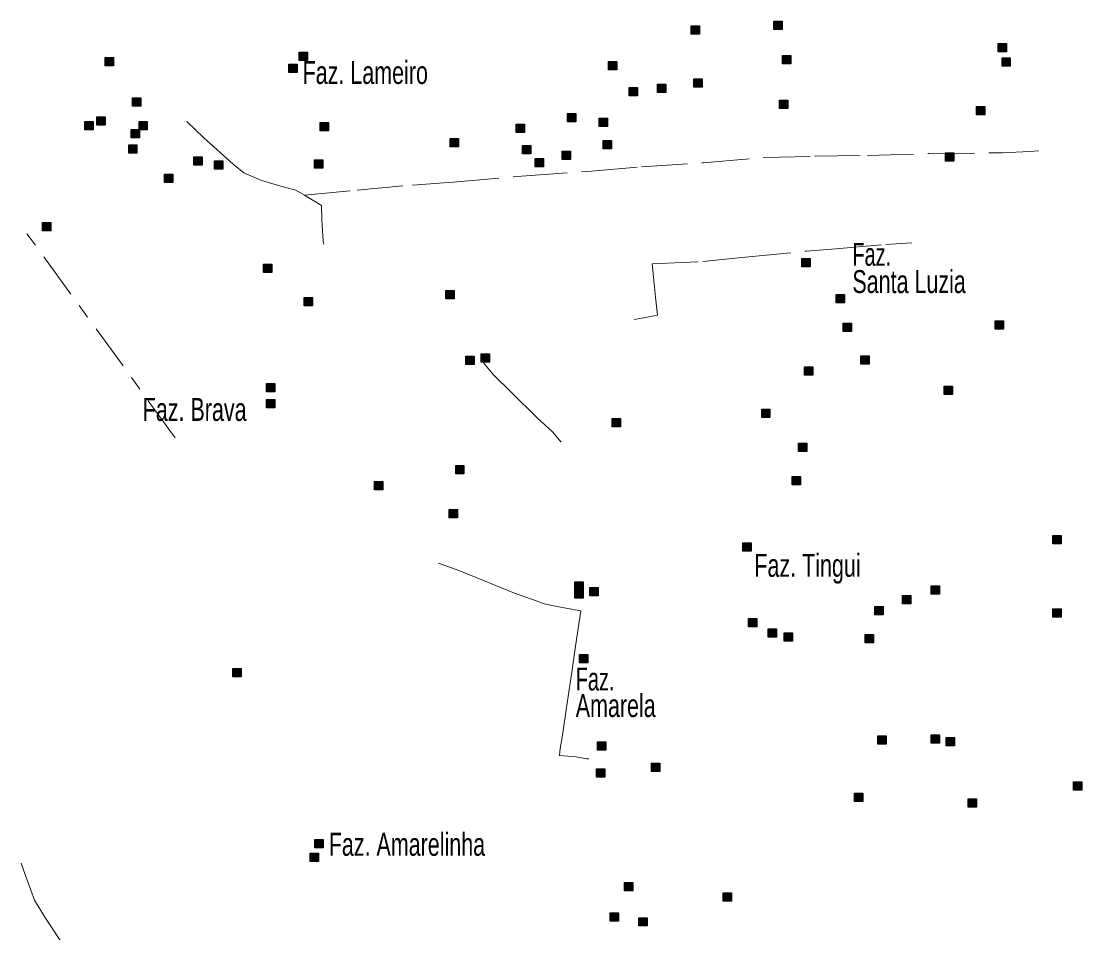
# Model space of a CAD drawing. Extents: x 445.6 to 500, y 8618.1 to 8673.4.
# Drawn here: x 492.59 to 499.98, y 8631.63 to 8637.98 of the extents above; entities that cross this region are included whole.
import ezdxf
from ezdxf.enums import TextEntityAlignment as Align

# ---------------------------------------------------------------- set-up
doc = ezdxf.new("R2010")
doc.units = 0
doc.header["$LTSCALE"] = 0.064
doc.linetypes.add('DOT_DASHED', pattern=[7.7, 5, -1.2, 0.3, -1.2])
doc.layers.add('2', color=7, linetype='Continuous', lineweight=25)
doc.layers.add('22', color=7, linetype='DOT_DASHED', lineweight=13)
doc.layers.add('61', color=7, linetype='Continuous')

msp = doc.modelspace()

# ---------------------------------------------------------------- hatches: boundary and pattern name
at = {"layer": '2'}
for points in [[(497.8344, 8637.9818), (497.8924, 8637.9818), (497.8924, 8637.9238), (497.8344, 8637.9238)], [(497.2581, 8637.9485), (497.3161, 8637.9485), (497.3161, 8637.8905), (497.2581, 8637.8905)], [(499.3972, 8637.8262), (499.4552, 8637.8262), (499.4552, 8637.7682), (499.3972, 8637.7682)], [(494.525, 8637.765), (494.583, 8637.765), (494.583, 8637.707), (494.525, 8637.707)], [(497.8954, 8637.7428), (497.9534, 8637.7428), (497.9534, 8637.6848), (497.8954, 8637.6848)], [(493.1709, 8637.7287), (493.2289, 8637.7287), (493.2289, 8637.6707), (493.1709, 8637.6707)], [(494.453, 8637.6817), (494.511, 8637.6817), (494.511, 8637.6237), (494.453, 8637.6237)], [(496.6804, 8637.7017), (496.7384, 8637.7017), (496.7384, 8637.6437), (496.6804, 8637.6437)], [(499.4249, 8637.7261), (499.4829, 8637.7261), (499.4829, 8637.6681), (499.4249, 8637.6681)], [(496.8241, 8637.5205), (496.8821, 8637.5205), (496.8821, 8637.4625), (496.8241, 8637.4625)], [(497.0236, 8637.5427), (497.0816, 8637.5427), (497.0816, 8637.4847), (497.0236, 8637.4847)], [(497.2772, 8637.5806), (497.3352, 8637.5806), (497.3352, 8637.5226), (497.2772, 8637.5226)], [(493.3631, 8637.4484), (493.4211, 8637.4484), (493.4211, 8637.3904), (493.3631, 8637.3904)], [(497.8732, 8637.4316), (497.9312, 8637.4316), (497.9312, 8637.3736), (497.8732, 8637.3736)], [(499.2475, 8637.3871), (499.3055, 8637.3871), (499.3055, 8637.3291), (499.2475, 8637.3291)], [(493.1137, 8637.315), (493.1717, 8637.315), (493.1717, 8637.257), (493.1137, 8637.257)], [(496.3954, 8637.3384), (496.4534, 8637.3384), (496.4534, 8637.2804), (496.3954, 8637.2804)], [(496.6167, 8637.3048), (496.6747, 8637.3048), (496.6747, 8637.2468), (496.6167, 8637.2468)], [(493.0306, 8637.2817), (493.0886, 8637.2817), (493.0886, 8637.2237), (493.0306, 8637.2237)], [(493.352, 8637.2261), (493.41, 8637.2261), (493.41, 8637.1681), (493.352, 8637.1681)], [(493.4074, 8637.2817), (493.4654, 8637.2817), (493.4654, 8637.2237), (493.4074, 8637.2237)], [(494.6709, 8637.2761), (494.7289, 8637.2761), (494.7289, 8637.2181), (494.6709, 8637.2181)], [(496.0372, 8637.2648), (496.0952, 8637.2648), (496.0952, 8637.2068), (496.0372, 8637.2068)], [(495.5772, 8637.1648), (495.6352, 8637.1648), (495.6352, 8637.1068), (495.5772, 8637.1068)], [(496.6435, 8637.1501), (496.7015, 8637.1501), (496.7015, 8637.0921), (496.6435, 8637.0921)], [(493.3353, 8637.1205), (493.3933, 8637.1205), (493.3933, 8637.0625), (493.3353, 8637.0625)], [(496.0815, 8637.1147), (496.1395, 8637.1147), (496.1395, 8637.0567), (496.0815, 8637.0567)], [(493.7898, 8637.0371), (493.8478, 8637.0371), (493.8478, 8636.9791), (493.7898, 8636.9791)], [(493.9338, 8637.0093), (493.9918, 8637.0093), (493.9918, 8636.9513), (493.9338, 8636.9513)], [(494.6321, 8637.0149), (494.6901, 8637.0149), (494.6901, 8636.9569), (494.6321, 8636.9569)], [(496.1702, 8637.0258), (496.2282, 8637.0258), (496.2282, 8636.9678), (496.1702, 8636.9678)], [(496.3586, 8637.0758), (496.4166, 8637.0758), (496.4166, 8637.0178), (496.3586, 8637.0178)], [(499.0314, 8637.0647), (499.0894, 8637.0647), (499.0894, 8637.0067), (499.0314, 8637.0067)], [(493.5847, 8636.9149), (493.6427, 8636.9149), (493.6427, 8636.8569), (493.5847, 8636.8569)], [(492.735, 8636.5785), (492.793, 8636.5785), (492.793, 8636.5205), (492.735, 8636.5205)], [(494.2765, 8636.2888), (494.3345, 8636.2888), (494.3345, 8636.2308), (494.2765, 8636.2308)], [(498.03, 8636.3275), (498.088, 8636.3275), (498.088, 8636.2695), (498.03, 8636.2695)], [(494.5591, 8636.0553), (494.6171, 8636.0553), (494.6171, 8635.9973), (494.5591, 8635.9973)], [(495.5474, 8636.1052), (495.6054, 8636.1052), (495.6054, 8636.0472), (495.5474, 8636.0472)], [(498.2683, 8636.0774), (498.3263, 8636.0774), (498.3263, 8636.0194), (498.2683, 8636.0194)], [(499.3767, 8635.8939), (499.4347, 8635.8939), (499.4347, 8635.8359), (499.3767, 8635.8359)], [(498.3182, 8635.8773), (498.3762, 8635.8773), (498.3762, 8635.8193), (498.3182, 8635.8193)], [(495.6874, 8635.6458), (495.7454, 8635.6458), (495.7454, 8635.5878), (495.6874, 8635.5878)], [(495.7927, 8635.6625), (495.8507, 8635.6625), (495.8507, 8635.6045), (495.7927, 8635.6045)], [(498.4401, 8635.6494), (498.4981, 8635.6494), (498.4981, 8635.5914), (498.4401, 8635.5914)], [(498.0467, 8635.5716), (498.1047, 8635.5716), (498.1047, 8635.5136), (498.0467, 8635.5136)], [(494.2965, 8635.4568), (494.3545, 8635.4568), (494.3545, 8635.3988), (494.2965, 8635.3988)], [(499.022, 8635.4382), (499.08, 8635.4382), (499.08, 8635.3802), (499.022, 8635.3802)], [(494.2965, 8635.3457), (494.3545, 8635.3457), (494.3545, 8635.2877), (494.2965, 8635.2877)], [(497.7491, 8635.2767), (497.8071, 8635.2767), (497.8071, 8635.2187), (497.7491, 8635.2187)], [(496.7071, 8635.2123), (496.7651, 8635.2123), (496.7651, 8635.1543), (496.7071, 8635.1543)], [(498.0058, 8635.0404), (498.0638, 8635.0404), (498.0638, 8634.9824), (498.0058, 8634.9824)], [(495.6154, 8634.8843), (495.6734, 8634.8843), (495.6734, 8634.8263), (495.6154, 8634.8263)], [(497.9614, 8634.807), (498.0194, 8634.807), (498.0194, 8634.749), (497.9614, 8634.749)], [(495.0501, 8634.7732), (495.1081, 8634.7732), (495.1081, 8634.7152), (495.0501, 8634.7152)], [(495.571, 8634.5786), (495.629, 8634.5786), (495.629, 8634.5206), (495.571, 8634.5206)], [(497.6179, 8634.3456), (497.6759, 8634.3456), (497.6759, 8634.2876), (497.6179, 8634.2876)], [(499.7791, 8634.3957), (499.8371, 8634.3957), (499.8371, 8634.3377), (499.7791, 8634.3377)], [(496.4466, 8634.0728), (496.5046, 8634.0728), (496.5046, 8634.0148), (496.4466, 8634.0148)], [(498.9312, 8634.0455), (498.9892, 8634.0455), (498.9892, 8633.9875), (498.9312, 8633.9875)], [(496.4466, 8634.0173), (496.5046, 8634.0173), (496.5046, 8633.9593), (496.4466, 8633.9593)], [(496.5519, 8634.0339), (496.6099, 8634.0339), (496.6099, 8633.9759), (496.5519, 8633.9759)], [(498.7317, 8633.9788), (498.7897, 8633.9788), (498.7897, 8633.9208), (498.7317, 8633.9208)], [(498.5378, 8633.901), (498.5958, 8633.901), (498.5958, 8633.843), (498.5378, 8633.843)], [(499.7791, 8633.8843), (499.8371, 8633.8843), (499.8371, 8633.8263), (499.7791, 8633.8263)], [(497.6567, 8633.8176), (497.7147, 8633.8176), (497.7147, 8633.7596), (497.6567, 8633.7596)], [(497.7952, 8633.7454), (497.8532, 8633.7454), (497.8532, 8633.6874), (497.7952, 8633.6874)], [(497.906, 8633.7176), (497.964, 8633.7176), (497.964, 8633.6596), (497.906, 8633.6596)], [(498.4713, 8633.7064), (498.5293, 8633.7064), (498.5293, 8633.6484), (498.4713, 8633.6484)], [(496.4799, 8633.567), (496.5379, 8633.567), (496.5379, 8633.509), (496.4799, 8633.509)], [(494.0609, 8633.4703), (494.1189, 8633.4703), (494.1189, 8633.4123), (494.0609, 8633.4123)], [(496.6035, 8632.9585), (496.6615, 8632.9585), (496.6615, 8632.9005), (496.6035, 8632.9005)], [(498.5599, 8633.0006), (498.6179, 8633.0006), (498.6179, 8632.9426), (498.5599, 8632.9426)], [(498.9312, 8633.0061), (498.9892, 8633.0061), (498.9892, 8632.9481), (498.9312, 8632.9481)], [(499.0365, 8632.9894), (499.0945, 8632.9894), (499.0945, 8632.9314), (499.0365, 8632.9314)], [(496.9803, 8632.8084), (497.0383, 8632.8084), (497.0383, 8632.7504), (496.9803, 8632.7504)], [(496.5979, 8632.7695), (496.6559, 8632.7695), (496.6559, 8632.7115), (496.5979, 8632.7115)], [(499.9232, 8632.6782), (499.9812, 8632.6782), (499.9812, 8632.6202), (499.9232, 8632.6202)], [(498.3961, 8632.5992), (498.4541, 8632.5992), (498.4541, 8632.5412), (498.3961, 8632.5412)], [(499.1885, 8632.5603), (499.2465, 8632.5603), (499.2465, 8632.5023), (499.1885, 8632.5023)], [(494.6334, 8632.2771), (494.6914, 8632.2771), (494.6914, 8632.2191), (494.6334, 8632.2191)], [(494.6001, 8632.1826), (494.6581, 8632.1826), (494.6581, 8632.1246), (494.6001, 8632.1246)], [(496.7922, 8631.9769), (496.8502, 8631.9769), (496.8502, 8631.9189), (496.7922, 8631.9189)], [(497.4817, 8631.9044), (497.5397, 8631.9044), (497.5397, 8631.8464), (497.4817, 8631.8464)], [(496.6924, 8631.7657), (496.7504, 8631.7657), (496.7504, 8631.7077), (496.6924, 8631.7077)], [(496.8919, 8631.7323), (496.9499, 8631.7323), (496.9499, 8631.6743), (496.8919, 8631.6743)]]:
    msp.add_hatch(color=256, dxfattribs=at).paths.add_polyline_path(points)

# ---------------------------------------------------------------- linework, layer by layer
for points in [[(497.8344, 8637.9818), (497.8924, 8637.9818), (497.8924, 8637.9238), (497.8344, 8637.9238)], [(497.2581, 8637.9485), (497.3161, 8637.9485), (497.3161, 8637.8905), (497.2581, 8637.8905)], [(499.3972, 8637.8262), (499.4552, 8637.8262), (499.4552, 8637.7682), (499.3972, 8637.7682)], [(494.525, 8637.765), (494.583, 8637.765), (494.583, 8637.707), (494.525, 8637.707)], [(497.8954, 8637.7428), (497.9534, 8637.7428), (497.9534, 8637.6848), (497.8954, 8637.6848)], [(493.1709, 8637.7287), (493.2289, 8637.7287), (493.2289, 8637.6707), (493.1709, 8637.6707)], [(494.453, 8637.6817), (494.511, 8637.6817), (494.511, 8637.6237), (494.453, 8637.6237)], [(496.6804, 8637.7017), (496.7384, 8637.7017), (496.7384, 8637.6437), (496.6804, 8637.6437)], [(499.4249, 8637.7261), (499.4829, 8637.7261), (499.4829, 8637.6681), (499.4249, 8637.6681)], [(496.8241, 8637.5205), (496.8821, 8637.5205), (496.8821, 8637.4625), (496.8241, 8637.4625)], [(497.0236, 8637.5427), (497.0816, 8637.5427), (497.0816, 8637.4847), (497.0236, 8637.4847)], [(497.2772, 8637.5806), (497.3352, 8637.5806), (497.3352, 8637.5226), (497.2772, 8637.5226)], [(493.3631, 8637.4484), (493.4211, 8637.4484), (493.4211, 8637.3904), (493.3631, 8637.3904)], [(497.8732, 8637.4316), (497.9312, 8637.4316), (497.9312, 8637.3736), (497.8732, 8637.3736)], [(499.2475, 8637.3871), (499.3055, 8637.3871), (499.3055, 8637.3291), (499.2475, 8637.3291)], [(493.1137, 8637.315), (493.1717, 8637.315), (493.1717, 8637.257), (493.1137, 8637.257)], [(496.3954, 8637.3384), (496.4534, 8637.3384), (496.4534, 8637.2804), (496.3954, 8637.2804)], [(496.6167, 8637.3048), (496.6747, 8637.3048), (496.6747, 8637.2468), (496.6167, 8637.2468)], [(493.0306, 8637.2817), (493.0886, 8637.2817), (493.0886, 8637.2237), (493.0306, 8637.2237)], [(493.352, 8637.2261), (493.41, 8637.2261), (493.41, 8637.1681), (493.352, 8637.1681)], [(493.4074, 8637.2817), (493.4654, 8637.2817), (493.4654, 8637.2237), (493.4074, 8637.2237)], [(494.6709, 8637.2761), (494.7289, 8637.2761), (494.7289, 8637.2181), (494.6709, 8637.2181)], [(496.0372, 8637.2648), (496.0952, 8637.2648), (496.0952, 8637.2068), (496.0372, 8637.2068)], [(495.5772, 8637.1648), (495.6352, 8637.1648), (495.6352, 8637.1068), (495.5772, 8637.1068)], [(496.6435, 8637.1501), (496.7015, 8637.1501), (496.7015, 8637.0921), (496.6435, 8637.0921)], [(493.3353, 8637.1205), (493.3933, 8637.1205), (493.3933, 8637.0625), (493.3353, 8637.0625)], [(496.0815, 8637.1147), (496.1395, 8637.1147), (496.1395, 8637.0567), (496.0815, 8637.0567)], [(493.7898, 8637.0371), (493.8478, 8637.0371), (493.8478, 8636.9791), (493.7898, 8636.9791)], [(493.9338, 8637.0093), (493.9918, 8637.0093), (493.9918, 8636.9513), (493.9338, 8636.9513)], [(494.6321, 8637.0149), (494.6901, 8637.0149), (494.6901, 8636.9569), (494.6321, 8636.9569)], [(496.1702, 8637.0258), (496.2282, 8637.0258), (496.2282, 8636.9678), (496.1702, 8636.9678)], [(496.3586, 8637.0758), (496.4166, 8637.0758), (496.4166, 8637.0178), (496.3586, 8637.0178)], [(499.0314, 8637.0647), (499.0894, 8637.0647), (499.0894, 8637.0067), (499.0314, 8637.0067)], [(493.5847, 8636.9149), (493.6427, 8636.9149), (493.6427, 8636.8569), (493.5847, 8636.8569)], [(492.735, 8636.5785), (492.793, 8636.5785), (492.793, 8636.5205), (492.735, 8636.5205)], [(494.2765, 8636.2888), (494.3345, 8636.2888), (494.3345, 8636.2308), (494.2765, 8636.2308)], [(498.03, 8636.3275), (498.088, 8636.3275), (498.088, 8636.2695), (498.03, 8636.2695)], [(494.5591, 8636.0553), (494.6171, 8636.0553), (494.6171, 8635.9973), (494.5591, 8635.9973)], [(495.5474, 8636.1052), (495.6054, 8636.1052), (495.6054, 8636.0472), (495.5474, 8636.0472)], [(498.2683, 8636.0774), (498.3263, 8636.0774), (498.3263, 8636.0194), (498.2683, 8636.0194)], [(499.3767, 8635.8939), (499.4347, 8635.8939), (499.4347, 8635.8359), (499.3767, 8635.8359)], [(498.3182, 8635.8773), (498.3762, 8635.8773), (498.3762, 8635.8193), (498.3182, 8635.8193)], [(495.6874, 8635.6458), (495.7454, 8635.6458), (495.7454, 8635.5878), (495.6874, 8635.5878)], [(495.7927, 8635.6625), (495.8507, 8635.6625), (495.8507, 8635.6045), (495.7927, 8635.6045)], [(498.4401, 8635.6494), (498.4981, 8635.6494), (498.4981, 8635.5914), (498.4401, 8635.5914)], [(498.0467, 8635.5716), (498.1047, 8635.5716), (498.1047, 8635.5136), (498.0467, 8635.5136)], [(494.2965, 8635.4568), (494.3545, 8635.4568), (494.3545, 8635.3988), (494.2965, 8635.3988)], [(499.022, 8635.4382), (499.08, 8635.4382), (499.08, 8635.3802), (499.022, 8635.3802)], [(494.2965, 8635.3457), (494.3545, 8635.3457), (494.3545, 8635.2877), (494.2965, 8635.2877)], [(497.7491, 8635.2767), (497.8071, 8635.2767), (497.8071, 8635.2187), (497.7491, 8635.2187)], [(496.7071, 8635.2123), (496.7651, 8635.2123), (496.7651, 8635.1543), (496.7071, 8635.1543)], [(498.0058, 8635.0404), (498.0638, 8635.0404), (498.0638, 8634.9824), (498.0058, 8634.9824)], [(495.6154, 8634.8843), (495.6734, 8634.8843), (495.6734, 8634.8263), (495.6154, 8634.8263)], [(497.9614, 8634.807), (498.0194, 8634.807), (498.0194, 8634.749), (497.9614, 8634.749)], [(495.0501, 8634.7732), (495.1081, 8634.7732), (495.1081, 8634.7152), (495.0501, 8634.7152)], [(495.571, 8634.5786), (495.629, 8634.5786), (495.629, 8634.5206), (495.571, 8634.5206)], [(497.6179, 8634.3456), (497.6759, 8634.3456), (497.6759, 8634.2876), (497.6179, 8634.2876)], [(499.7791, 8634.3957), (499.8371, 8634.3957), (499.8371, 8634.3377), (499.7791, 8634.3377)], [(496.4466, 8634.0728), (496.5046, 8634.0728), (496.5046, 8634.0148), (496.4466, 8634.0148)], [(498.9312, 8634.0455), (498.9892, 8634.0455), (498.9892, 8633.9875), (498.9312, 8633.9875)], [(496.4466, 8634.0173), (496.5046, 8634.0173), (496.5046, 8633.9593), (496.4466, 8633.9593)], [(496.5519, 8634.0339), (496.6099, 8634.0339), (496.6099, 8633.9759), (496.5519, 8633.9759)], [(498.7317, 8633.9788), (498.7897, 8633.9788), (498.7897, 8633.9208), (498.7317, 8633.9208)], [(498.5378, 8633.901), (498.5958, 8633.901), (498.5958, 8633.843), (498.5378, 8633.843)], [(499.7791, 8633.8843), (499.8371, 8633.8843), (499.8371, 8633.8263), (499.7791, 8633.8263)], [(497.6567, 8633.8176), (497.7147, 8633.8176), (497.7147, 8633.7596), (497.6567, 8633.7596)], [(497.7952, 8633.7454), (497.8532, 8633.7454), (497.8532, 8633.6874), (497.7952, 8633.6874)], [(497.906, 8633.7176), (497.964, 8633.7176), (497.964, 8633.6596), (497.906, 8633.6596)], [(498.4713, 8633.7064), (498.5293, 8633.7064), (498.5293, 8633.6484), (498.4713, 8633.6484)], [(496.4799, 8633.567), (496.5379, 8633.567), (496.5379, 8633.509), (496.4799, 8633.509)], [(494.0609, 8633.4703), (494.1189, 8633.4703), (494.1189, 8633.4123), (494.0609, 8633.4123)], [(496.6035, 8632.9585), (496.6615, 8632.9585), (496.6615, 8632.9005), (496.6035, 8632.9005)], [(498.5599, 8633.0006), (498.6179, 8633.0006), (498.6179, 8632.9426), (498.5599, 8632.9426)], [(498.9312, 8633.0061), (498.9892, 8633.0061), (498.9892, 8632.9481), (498.9312, 8632.9481)], [(499.0365, 8632.9894), (499.0945, 8632.9894), (499.0945, 8632.9314), (499.0365, 8632.9314)], [(496.9803, 8632.8084), (497.0383, 8632.8084), (497.0383, 8632.7504), (496.9803, 8632.7504)], [(496.5979, 8632.7695), (496.6559, 8632.7695), (496.6559, 8632.7115), (496.5979, 8632.7115)], [(499.9232, 8632.6782), (499.9812, 8632.6782), (499.9812, 8632.6202), (499.9232, 8632.6202)], [(498.3961, 8632.5992), (498.4541, 8632.5992), (498.4541, 8632.5412), (498.3961, 8632.5412)], [(499.1885, 8632.5603), (499.2465, 8632.5603), (499.2465, 8632.5023), (499.1885, 8632.5023)], [(494.6334, 8632.2771), (494.6914, 8632.2771), (494.6914, 8632.2191), (494.6334, 8632.2191)], [(494.6001, 8632.1826), (494.6581, 8632.1826), (494.6581, 8632.1246), (494.6001, 8632.1246)], [(496.7922, 8631.9769), (496.8502, 8631.9769), (496.8502, 8631.9189), (496.7922, 8631.9189)], [(497.4817, 8631.9044), (497.5397, 8631.9044), (497.5397, 8631.8464), (497.4817, 8631.8464)], [(496.6924, 8631.7657), (496.7504, 8631.7657), (496.7504, 8631.7077), (496.6924, 8631.7077)], [(496.8919, 8631.7323), (496.9499, 8631.7323), (496.9499, 8631.6743), (496.8919, 8631.6743)]]:
    msp.add_lwpolyline(points, close=True, dxfattribs=at)
at = {"layer": '22'}
msp.add_line((493.6603, 8635.0766), (492.6134, 8636.518), dxfattribs=at)
for points in [[(493.742, 8637.2826), (493.8599, 8637.168), (494.0633, 8636.9861), (494.1393, 8636.9254), (494.2607, 8636.8708), (494.4278, 8636.8223), (494.5007, 8636.8041), (494.5611, 8636.7683)], [(494.5611, 8636.7683), (494.9295, 8636.8033), (495.3152, 8636.8397), (495.5976, 8636.8609), (496.074, 8636.9008), (496.563, 8636.9372), (496.9122, 8636.9675), (497.3435, 8636.9948), (497.7671, 8637.0315), (498.1163, 8637.0406), (498.4868, 8637.0467), (498.914, 8637.0589), (499.4273, 8637.065), (499.6156, 8637.0741), (499.6824, 8637.0771)], [(494.5611, 8636.7683), (494.6798, 8636.698), (494.6829, 8636.5979), (494.6926, 8636.4485), (494.6956, 8636.4273)], [(496.8595, 8635.9027), (496.9146, 8635.9119), (497.0216, 8635.9333), (497.0094, 8636.0584), (496.9849, 8636.2904), (497.3395, 8636.3056), (497.6329, 8636.3361), (498.0608, 8636.3789), (498.2656, 8636.3941), (498.6154, 8636.4254), (498.7957, 8636.4376)], [(495.8103, 8635.5997), (495.8786, 8635.5157), (496.0041, 8635.3929), (496.1838, 8635.2159), (496.2896, 8635.1201), (496.3512, 8635.0464)], [(495.4948, 8634.2045), (495.6454, 8634.1503), (495.8095, 8634.0837), (496.0248, 8633.9942), (496.176, 8633.9404), (496.2324, 8633.9199), (496.3452, 8633.8969), (496.4887, 8633.8713), (496.4502, 8633.6256), (496.4272, 8633.4592), (496.3869, 8633.1812), (496.3612, 8633.0046), (496.3433, 8632.9125), (496.3386, 8632.8628), (496.4565, 8632.8526), (496.5308, 8632.8398), (496.5446, 8632.8398)], [(492.586, 8632.1131), (492.6277, 8631.9946), (492.679, 8631.8537), (492.756, 8631.7288), (492.8779, 8631.5431), (492.942, 8631.4182), (492.9933, 8631.3093), (493.0254, 8631.2581), (493.1062, 8631.0701), (493.2248, 8630.8364), (493.3211, 8630.6314), (493.3916, 8630.5033), (493.53, 8630.2191), (493.6102, 8630.0526), (493.8026, 8629.6843), (493.9734, 8629.3235), (494.0247, 8629.2274), (494.0492, 8629.1839)]]:
    msp.add_lwpolyline(points, dxfattribs=at)

# ---------------------------------------------------------------- texts
at = {"layer": '61'}
for s, width, p in [('Faz. Lameiro', 0.7, (494.548, 8637.5444)), ('Faz.', 0.65, (498.3816, 8636.2766)), ('Santa Luzia', 0.7, (498.3816, 8636.0866)), ('Faz.', 0.65, (496.4526, 8633.316)), ('Amarela', 0.7, (496.4526, 8633.131)), ('Faz. Amarelinha', 0.7, (494.7304, 8632.1638))]:
    msp.add_text(s, height=0.16, dxfattribs=dict(at, width=width)).set_placement(p)
at = {"layer": '61', "width": 0.7}
msp.add_text('Faz. Brava', height=0.16, dxfattribs=at).set_placement((494.1574, 8635.1955), align=Align.RIGHT)
msp.add_text('Faz. Tingui', height=0.16, dxfattribs=at).set_placement((498.0686, 8634.1085), align=Align.CENTER)

doc.saveas('drawing.dxf')
